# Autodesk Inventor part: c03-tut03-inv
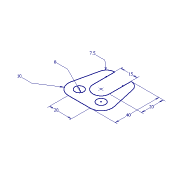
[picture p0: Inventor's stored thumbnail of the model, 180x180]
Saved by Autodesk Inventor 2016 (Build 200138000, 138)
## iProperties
Created: 2010-01
Part Number: c03-tut03-inv
Document SubType Name: Modeling
Designer: CADSoft
Density: 1 g/cm^3
Material: Generic
Appearance: Default
Author: CADSoft
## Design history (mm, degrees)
sketch "Sketch1"
  geometry: L1 (-10, -20)-(10, -20); L2 (19.756, -7.805)-(14.817, 14.146); L3 (7.5, 20)-(7.5, 0); L4 (-7.5, 0)-(-7.5, 20); L5 (-14.817, 14.146)-(-19.756, -7.805); C1 r 4 at (-10, -10); C2 r 4 at (10, -10); A1 r 10 centre (10, -10) between (10, -20) and (19.756, -7.805); A2 r 7.5 centre (7.5, 12.5) between (14.817, 14.146) and (7.5, 20); A3 r 7.5 centre (0, 0) between (-7.5, 0) and (7.5, 0); A4 r 7.5 centre (-7.5, 12.5) between (-7.5, 20) and (-14.817, 14.146); A5 r 10 centre (-10, -10) between (-19.756, -7.805) and (-10, -20); 2 further points
  constraints: 10 end point, 10 point on circle, 8 tangent, 7 centre point, 4 coincident, 3 equal radius, 2 equal length, 2 point on line, 2 vertical, 1 horizontal, 1 other
  dimensions: "d0" = 20 distance of L1.start L1.end; "d1" = 7.5 radius of A4; "d2" = 10 radius of A5; "d3" = 15 distance between parallel lines of L3 L4; "d4" = 20 distance of L3.start L3.end; "d5" = 40 distance from line of L1 L3.start; "d6" = 8 diameter of C1
